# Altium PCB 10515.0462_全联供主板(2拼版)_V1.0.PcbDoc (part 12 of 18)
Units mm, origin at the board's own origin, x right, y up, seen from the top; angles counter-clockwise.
Board outline 282 x 198 mm, 2 copper layers (Top Layer, Bottom Layer); 716 components, 0 nets, 2364 pads, 1800 vias.
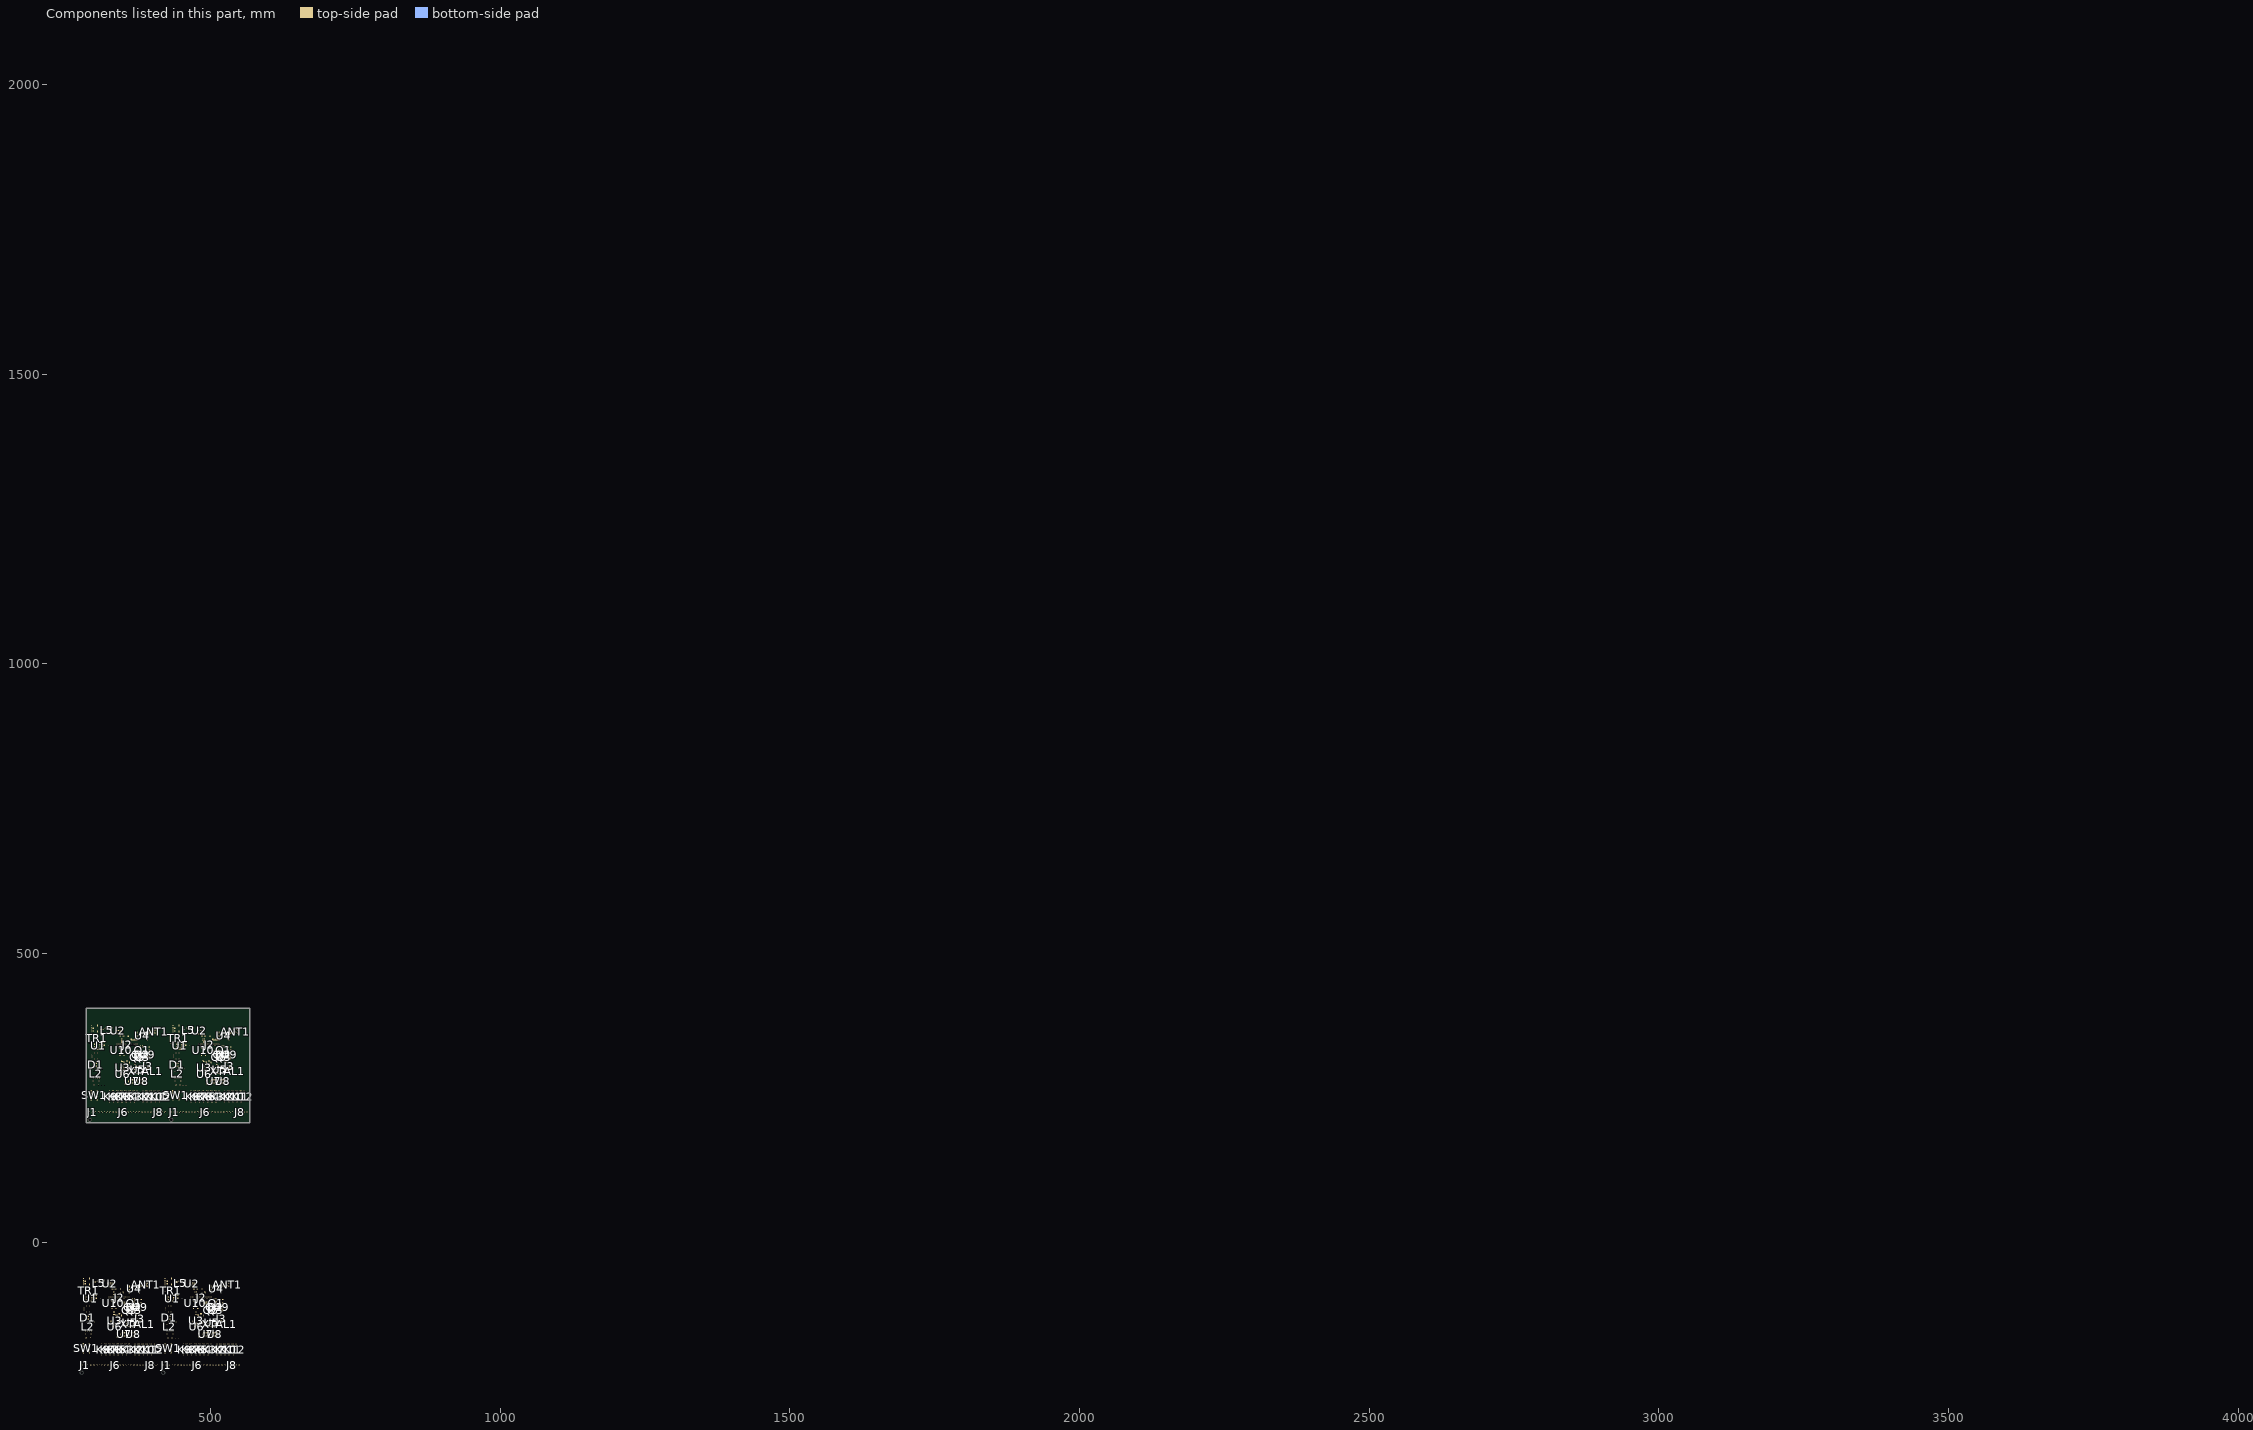
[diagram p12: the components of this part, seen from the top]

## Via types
v1: diameter 0.7, hole 0.4, Top Layer to Bottom Layer, tented both sides, 1800 vias

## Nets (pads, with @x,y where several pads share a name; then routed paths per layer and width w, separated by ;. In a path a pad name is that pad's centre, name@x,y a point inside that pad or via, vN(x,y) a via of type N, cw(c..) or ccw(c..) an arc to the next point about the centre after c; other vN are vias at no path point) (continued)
copper on no net: (continued)
  Top Layer w1: 276.62,-91.985 278.5,-90.106 283.326,-90.106 ; 276.62,-81.985 278.872,-81.985 280.049,-83.162 280.049,-83.984 ; 279.041,-82.154 cw(c277.211,-83.984) 279.799,-83.984 ; 280.049,-73.984 280.049,-76.895 281.412,-78.258 288.397,-78.258 289.605,-77.05 289.605,-76.099 ; 280.38,-97.135 cw(c277.147,-100.368) 281.72,-100.368 ; 280.557,-96.958 283.28,-96.958 ; 281.72,-101.002 281.72,-96.978 ; 282.206,-90.106 ccw(c282.206,-88.428) 283.393,-89.614 ; 284.972,-100.826 ccw(c282.446,-98.3) 286.018,-98.3 ; 285.149,-101.002 286.018,-100.133 286.018,-97.852 ; 285.735,-98.235 cw(c285.052,-98.918) 286.018,-98.918 cw(c286.984,-98.918) 286.301,-98.235 ; 286.111,-136.551 289.319,-136.551 ; 286.301,-93.302 ccw(c288.019,-91.584) 288.019,-94.013 ; 286.547,-94.013 289.059,-94.013 ; 288.431,-102.399 290.59,-102.399 ; 288.431,-100.099 290.59,-100.099 ; 289.009,-77.646 ccw(c287.924,-76.561) 289.33,-75.947 ; 289.059,-97.562 v1(289.059,-96.945) v1(289.685,-96.945) 289.794,-97.054 289.794,-97.308 ; 289.059,-94.895 289.059,-94.013 ; 289.059,-91.868 cw(c291.647,-91.868) 289.817,-90.039 ; 289.605,-89.826 289.059,-90.372 289.059,-94.013 ; 290.249,344.61 292.128,346.49 296.954,346.49 ; 290.249,354.61 292.501,354.61 293.678,353.433 293.678,352.611 ; 290.677,-102.486 290.59,-102.399 ; 292.67,354.441 cw(c290.839,352.611) 293.428,352.611 ; 293.003,-100.099 295.162,-100.099 ; 293.678,362.611 293.678,359.701 295.041,358.337 302.026,358.337 303.234,359.545 303.234,360.496 ; 294.009,339.461 cw(c290.775,336.227) 295.348,336.227 ; 294.186,339.637 296.909,339.637 ; 295.348,335.593 295.348,339.618 ; 295.605,-89.826 296.226,-90.447 302.209,-90.447 ; 295.817,-89.614 ccw(c297.829,-87.603) 297.829,-90.447 ; 295.835,346.49 ccw(c295.835,348.168) 297.022,346.981 ; 297.979,-102.399 ccw(c297.979,-100.989) 298.976,-101.986 ; 298.601,335.77 ccw(c296.075,338.296) 299.647,338.296 ; 298.777,335.593 299.647,336.462 299.647,338.743 ; 299.226,-101.986 298.813,-102.399 295.162,-102.399 293.003,-102.399 290.59,-102.399 ; 299.226,-99.986 299.48,-99.732 299.48,-97.319 ; 299.364,338.36 cw(c298.681,337.677) 299.647,337.677 cw(c300.612,337.677) 299.93,338.36 ; 299.48,-95.019 301.981,-95.019 ; 299.74,300.044 302.948,300.044 ; 299.93,343.294 ccw(c301.648,345.012) 301.648,342.582 ; 300.176,342.582 302.688,342.582 ; 300.296,-90.447 ccw(c300.296,-88.246) 301.853,-89.803 ; 300.469,-95.019 cw(c300.469,-96.976) 301.853,-95.593 ; 300.847,-95.019 ccw(c300.847,-93.596) 301.853,-94.603 ; 301.02,-90.447 cw(c301.02,-91.626) 301.853,-90.793 ; 302.06,334.196 304.219,334.196 ; 302.06,336.496 304.219,336.496 ; 302.638,358.949 ccw(c301.553,360.035) 302.959,360.649 ; 302.688,339.033 v1(302.688,339.65) v1(303.314,339.65) 303.423,339.541 303.423,339.287 ; 302.688,341.7 302.688,342.582 ; 302.688,344.727 cw(c305.276,344.727) 303.446,346.557 ; 303.234,346.769 302.688,346.223 302.688,342.582 ; 304.306,334.109 304.219,334.196 ; 306.632,336.496 308.791,336.496 ; 309.234,346.769 309.855,346.148 315.838,346.148 ; 309.446,346.981 ccw(c311.457,348.993) 311.457,346.148 ; 311.608,334.196 ccw(c311.608,335.606) 312.605,334.609 ; 312.855,334.609 312.442,334.196 308.791,334.196 306.632,334.196 304.219,334.196 ; 312.855,336.609 313.109,336.863 313.109,339.276 ; 313.109,341.576 315.61,341.576 ; 313.925,346.148 ccw(c313.925,348.35) 315.482,346.793 ; 314.098,341.576 cw(c314.098,339.619) 315.482,341.003 ; 314.475,341.576 ccw(c314.475,342.999) 315.482,341.993 ; 314.648,346.148 cw(c314.648,344.97) 315.482,345.803 ; 327.499,-75.475 328.909,-74.066 330.801,-74.066 330.801,-78.397 330.058,-79.14 ; 327.547,-74.48 ccw(c327.839,-72.997) 328.909,-74.066 ; 330.058,-80.545 cw(c331.141,-80.545) 330.927,-79.483 ; 330.484,-75.273 ccw(c329.471,-74.26) 330.894,-74.093 ; 330.801,-78.158 ccw(c331.84,-78.158) 331.105,-78.893 ; 330.801,-74.956 330.058,-75.699 330.058,-79.14 ; 331.201,-79.207 ccw(c332.895,-79.537) 331.675,-80.757 ; 332.075,-86.777 332.075,-84.237 332.075,-81.157 330.058,-79.14 ; 332.075,-82.312 330.058,-80.295 330.058,-79.14 ; 332.343,-69.008 v1(333.101,-69.008) 334.161,-69.008 335.658,-70.505 335.658,-79.14 334.361,-80.437 334.361,-82.83 ; 334.361,-86.777 334.361,-84.237 334.361,-82.83 ; 334.361,-81.185 cw(c336.902,-81.185) 335.105,-79.388 ; 334.361,-80.529 cw(c335.573,-80.529) 335.018,-79.451 ; 335.658,-80.273 334.361,-81.57 334.361,-82.83 ; 341.128,361.12 342.537,362.53 344.43,362.53 344.43,358.198 343.687,357.455 ; 341.176,362.115 ccw(c341.468,363.599) 342.537,362.53 ; 343.687,356.051 cw(c344.77,356.051) 344.556,357.112 ; 344.113,361.323 ccw(c343.1,362.336) 344.523,362.503 ; 344.43,358.438 ccw(c345.469,358.438) 344.734,357.703 ; 344.43,361.639 343.687,360.896 343.687,357.455 ; 344.83,357.388 ccw(c346.524,357.058) 345.304,355.838 ; 345.704,349.818 345.704,352.358 345.704,355.438 343.687,357.455 ; 345.704,354.283 343.687,356.301 343.687,357.455 ; 345.971,367.587 v1(346.73,367.587) 347.79,367.587 349.287,366.09 349.287,357.455 347.99,356.158 347.99,353.765 ; 347.99,349.818 347.99,352.358 347.99,353.765 ; 347.99,355.411 cw(c350.531,355.411) 348.734,357.208 ; 347.99,356.067 cw(c349.202,356.067) 348.647,357.144 ; 349.287,356.322 347.99,355.025 347.99,353.765 ; 385.033,-74.482 390.113,-74.482 390.113,-69.402 385.033,-69.402 ; 385.74,-75.189 cw(c387.447,-76.896) 387.447,-74.482 cw(c387.447,-72.068) 385.74,-73.775 ; 385.74,-70.109 cw(c387.447,-71.816) 387.447,-69.402 cw(c387.447,-66.988) 385.74,-68.695 ; 389.406,-75.189 ccw(c387.698,-76.896) 387.698,-74.482 ccw(c387.698,-72.068) 389.406,-73.775 ccw(c387.698,-72.068) 390.113,-72.068 ccw(c392.527,-72.068) 390.82,-73.775 ; 389.406,-68.695 cw(c387.698,-66.988) 387.698,-69.402 cw(c387.698,-71.816) 389.406,-70.109 cw(c387.698,-71.816) 390.113,-71.816 cw(c392.527,-71.816) 390.82,-70.109 ; 398.661,362.114 403.741,362.114 403.741,367.194 398.661,367.194 ; 399.369,361.406 cw(c401.076,359.699) 401.076,362.114 cw(c401.076,364.528) 399.369,362.821 ; 399.369,366.486 cw(c401.076,364.779) 401.076,367.194 cw(c401.076,369.608) 399.369,367.901 ; 403.034,361.406 ccw(c401.327,359.699) 401.327,362.114 ccw(c401.327,364.528) 403.034,362.821 ccw(c401.327,364.528) 403.741,364.528 ccw(c406.156,364.528) 404.449,362.821 ; 403.034,367.901 cw(c401.327,369.608) 401.327,367.194 cw(c401.327,364.779) 403.034,366.486 cw(c401.327,364.779) 403.741,364.779 cw(c406.156,364.779) 404.449,366.486 ; 417.62,-91.985 419.5,-90.106 424.326,-90.106 ; 417.62,-81.985 419.872,-81.985 421.049,-83.162 421.049,-83.984 ; 420.041,-82.154 cw(c418.211,-83.984) 420.799,-83.984 ; 421.049,-73.984 421.049,-76.895 422.412,-78.258 429.397,-78.258 430.605,-77.05 430.605,-76.099 ; 421.38,-97.135 cw(c418.147,-100.368) 422.72,-100.368 ; 421.557,-96.958 424.28,-96.958 ; 422.72,-101.002 422.72,-96.978 ; 423.206,-90.106 ccw(c423.206,-88.428) 424.393,-89.614 ; 425.972,-100.826 ccw(c423.446,-98.3) 427.018,-98.3 ; 426.149,-101.002 427.018,-100.133 427.018,-97.852 ; 426.735,-98.235 cw(c426.052,-98.918) 427.018,-98.918 cw(c427.984,-98.918) 427.301,-98.235 ; 427.111,-136.551 430.319,-136.551 ; 427.301,-93.302 ccw(c429.019,-91.584) 429.019,-94.013 ; 427.547,-94.013 430.059,-94.013 ; 429.431,-102.399 431.59,-102.399 ; 429.431,-100.099 431.59,-100.099 ; 430.009,-77.646 ccw(c428.924,-76.561) 430.33,-75.947 ; 430.059,-97.562 v1(430.059,-96.945) v1(430.685,-96.945) 430.794,-97.054 430.794,-97.308 ; 430.059,-94.895 430.059,-94.013 ; 430.059,-91.868 cw(c432.647,-91.868) 430.817,-90.039 ; 430.605,-89.826 430.059,-90.372 430.059,-94.013 ; 431.249,344.61 433.128,346.49 437.954,346.49 ; 431.249,354.61 433.501,354.61 434.678,353.433 434.678,352.611 ; 431.677,-102.486 431.59,-102.399 ; 433.67,354.441 cw(c431.839,352.611) 434.428,352.611 ; 434.003,-100.099 436.162,-100.099 ; 434.678,362.611 434.678,359.701 436.041,358.337 443.026,358.337 444.234,359.545 444.234,360.496 ; 435.009,339.461 cw(c431.775,336.227) 436.348,336.227 ; 435.186,339.637 437.909,339.637 ; 436.348,335.593 436.348,339.618 ; 436.605,-89.826 437.226,-90.447 443.209,-90.447 ; 436.817,-89.614 ccw(c438.829,-87.603) 438.829,-90.447 ; 436.835,346.49 ccw(c436.835,348.168) 438.022,346.981 ; 438.979,-102.399 ccw(c438.979,-100.989) 439.976,-101.986 ; 439.601,335.77 ccw(c437.075,338.296) 440.647,338.296 ; 439.777,335.593 440.647,336.462 440.647,338.743 ; 440.226,-101.986 439.813,-102.399 436.162,-102.399 434.003,-102.399 431.59,-102.399 ; 440.226,-99.986 440.48,-99.732 440.48,-97.319 ; 440.364,338.36 cw(c439.681,337.677) 440.647,337.677 cw(c441.612,337.677) 440.93,338.36 ; 440.48,-95.019 442.981,-95.019 ; 440.74,300.044 443.948,300.044 ; 440.93,343.294 ccw(c442.648,345.012) 442.648,342.582 ; 441.176,342.582 443.688,342.582 ; 441.296,-90.447 ccw(c441.296,-88.246) 442.853,-89.803 ; 441.469,-95.019 cw(c441.469,-96.976) 442.853,-95.593 ; 441.847,-95.019 ccw(c441.847,-93.596) 442.853,-94.603 ; 442.02,-90.447 cw(c442.02,-91.626) 442.853,-90.793 ; 443.06,334.196 445.219,334.196 ; 443.06,336.496 445.219,336.496 ; 443.638,358.949 ccw(c442.553,360.035) 443.959,360.649 ; 443.688,339.033 v1(443.688,339.65) v1(444.314,339.65) 444.423,339.541 444.423,339.287 ; 443.688,341.7 443.688,342.582 ; 443.688,344.727 cw(c446.276,344.727) 444.446,346.557 ; 444.234,346.769 443.688,346.223 443.688,342.582 ; 445.306,334.109 445.219,334.196 ; 447.632,336.496 449.791,336.496 ; 450.234,346.769 450.855,346.148 456.838,346.148 ; 450.446,346.981 ccw(c452.457,348.993) 452.457,346.148 ; 452.608,334.196 ccw(c452.608,335.606) 453.605,334.609 ; 453.855,334.609 453.442,334.196 449.791,334.196 447.632,334.196 445.219,334.196 ; 453.855,336.609 454.109,336.863 454.109,339.276 ; 454.109,341.576 456.61,341.576 ; 454.925,346.148 ccw(c454.925,348.35) 456.482,346.793 ; 455.098,341.576 cw(c455.098,339.619) 456.482,341.003 ; 455.475,341.576 ccw(c455.475,342.999) 456.482,341.993 ; 455.648,346.148 cw(c455.648,344.97) 456.482,345.803 ; 468.499,-75.475 469.909,-74.066 471.801,-74.066 471.801,-78.397 471.058,-79.14 ; 468.547,-74.48 ccw(c468.839,-72.997) 469.909,-74.066 ; 471.058,-80.545 cw(c472.141,-80.545) 471.927,-79.483 ; 471.484,-75.273 ccw(c470.471,-74.26) 471.894,-74.093 ; 471.801,-78.158 ccw(c472.84,-78.158) 472.105,-78.893 ; 471.801,-74.956 471.058,-75.699 471.058,-79.14 ; 472.201,-79.207 ccw(c473.895,-79.537) 472.675,-80.757 ; 473.075,-86.777 473.075,-84.237 473.075,-81.157 471.058,-79.14 ; 473.075,-82.312 471.058,-80.295 471.058,-79.14 ; 473.343,-69.008 v1(474.101,-69.008) 475.161,-69.008 476.658,-70.505 476.658,-79.14 475.361,-80.437 475.361,-82.83 ; 475.361,-86.777 475.361,-84.237 475.361,-82.83 ; 475.361,-81.185 cw(c477.902,-81.185) 476.105,-79.388 ; 475.361,-80.529 cw(c476.573,-80.529) 476.018,-79.451 ; 476.658,-80.273 475.361,-81.57 475.361,-82.83 ; 482.128,361.12 483.537,362.53 485.43,362.53 485.43,358.198 484.687,357.455 ; 482.176,362.115 ccw(c482.468,363.599) 483.537,362.53 ; 484.687,356.051 cw(c485.77,356.051) 485.556,357.112 ; 485.113,361.323 ccw(c484.1,362.336) 485.523,362.503 ; 485.43,358.438 ccw(c486.469,358.438) 485.734,357.703 ; 485.43,361.639 484.687,360.896 484.687,357.455 ; 485.83,357.388 ccw(c487.524,357.058) 486.304,355.838 ; 486.704,349.818 486.704,352.358 486.704,355.438 484.687,357.455 ; 486.704,354.283 484.687,356.301 484.687,357.455 ; 486.971,367.587 v1(487.73,367.587) 488.79,367.587 490.287,366.09 490.287,357.455 488.99,356.158 488.99,353.765 ; 488.99,349.818 488.99,352.358 488.99,353.765 ; 488.99,355.411 cw(c491.531,355.411) 489.734,357.208 ; 488.99,356.067 cw(c490.202,356.067) 489.647,357.144 ; 490.287,356.322 488.99,355.025 488.99,353.765 ; 526.033,-74.482 531.113,-74.482 531.113,-69.402 526.033,-69.402 ; 526.74,-75.189 cw(c528.447,-76.896) 528.447,-74.482 cw(c528.447,-72.068) 526.74,-73.775 ; 526.74,-70.109 cw(c528.447,-71.816) 528.447,-69.402 cw(c528.447,-66.988) 526.74,-68.695 ; 530.406,-75.189 ccw(c528.698,-76.896) 528.698,-74.482 ccw(c528.698,-72.068) 530.406,-73.775 ccw(c528.698,-72.068) 531.113,-72.068 ccw(c533.527,-72.068) 531.82,-73.775 ; 530.406,-68.695 cw(c528.698,-66.988) 528.698,-69.402 cw(c528.698,-71.816) 530.406,-70.109 cw(c528.698,-71.816) 531.113,-71.816 cw(c533.527,-71.816) 531.82,-70.109 ; 539.661,362.114 544.741,362.114 544.741,367.194 539.661,367.194 ; 540.369,361.406 cw(c542.076,359.699) 542.076,362.114 cw(c542.076,364.528) 540.369,362.821 ; 540.369,366.486 cw(c542.076,364.779) 542.076,367.194 cw(c542.076,369.608) 540.369,367.901 ; 544.034,361.406 ccw(c542.327,359.699) 542.327,362.114 ccw(c542.327,364.528) 544.034,362.821 ccw(c542.327,364.528) 544.741,364.528 ccw(c547.156,364.528) 545.449,362.821 ; 544.034,367.901 cw(c542.327,369.608) 542.327,367.194 cw(c542.327,364.779) 544.034,366.486 cw(c542.327,364.779) 544.741,364.779 cw(c547.156,364.779) 545.449,366.486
